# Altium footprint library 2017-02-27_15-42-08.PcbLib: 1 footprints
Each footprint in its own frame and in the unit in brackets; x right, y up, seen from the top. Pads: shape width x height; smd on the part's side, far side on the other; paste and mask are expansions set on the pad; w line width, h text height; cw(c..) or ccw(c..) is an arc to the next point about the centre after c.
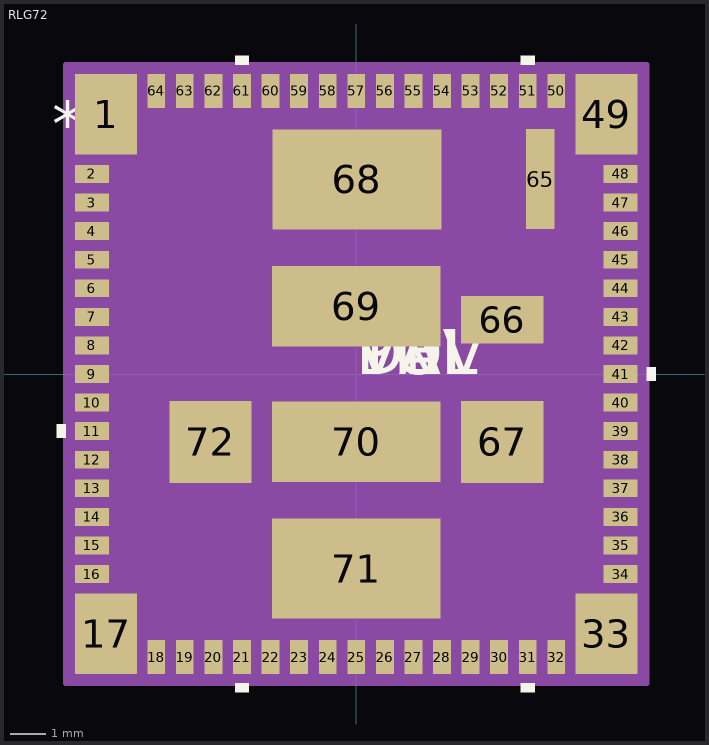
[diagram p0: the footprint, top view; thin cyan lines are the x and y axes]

## RLG72 [mm]
pads (72):
  rect 1.735x2.25 / inner round 1.524 / far side round 1.524 all layers, no hole: 1(-7.005,7.27) 17(-7.005,-7.27) 33(7.005,-7.27) 49(7.005,7.27)
  rect 0.95x0.5 smd paste-0.25: 2(-7.4,5.6) 3(-7.4,4.8) 4(-7.4,4) 5(-7.4,3.2) 6(-7.4,2.4) 7(-7.4,1.6) 8(-7.4,0.8) 9(-7.4,0) 10(-7.4,-0.8) 11(-7.4,-1.6) 12(-7.4,-2.4) 13(-7.4,-3.2) 14(-7.4,-4) 15(-7.4,-4.8) 16(-7.4,-5.6) 34(7.4,-5.6) 35(7.4,-4.8) 36(7.4,-4) 37(7.4,-3.2) 38(7.4,-2.4) 39(7.4,-1.6) 40(7.4,-0.8) 41(7.4,0) 42(7.4,0.8) 43(7.4,1.6) 44(7.4,2.4) 45(7.4,3.2) 46(7.4,4) 47(7.4,4.8) 48(7.4,5.6)
  rect 0.5x0.95 smd paste-0.25: 18(-5.6,-7.925) 19(-4.8,-7.925) 20(-4,-7.925) 21(-3.2,-7.925) 22(-2.4,-7.925) 23(-1.6,-7.925) 24(-0.8,-7.925) 25(0,-7.925) 26(0.8,-7.925) 27(1.6,-7.925) 28(2.4,-7.925) 29(3.2,-7.925) 30(4,-7.925) 31(4.8,-7.925) 32(5.6,-7.925) 50(5.6,7.925) 51(4.8,7.925) 52(4,7.925) 53(3.2,7.925) 54(2.4,7.925) 55(1.6,7.925) 56(0.8,7.925) 57(0,7.925) 58(-0.8,7.925) 59(-1.6,7.925) 60(-2.4,7.925) 61(-3.2,7.925) 62(-4,7.925) 63(-4.8,7.925) 64(-5.6,7.925)
  rect 0.8x2.8 smd paste-1.387: 65(5.15,5.453)
  rect 2.3x1.33 smd paste-1.137: 66(4.085,1.515)
  rect 2.3x2.3 smd paste-1.137: 67(4.085,-1.9) 72(-4.085,-1.9)
  rect 4.72x2.8 smd paste-2.347: 68(0.02,5.451) 71(0,-5.451)
  rect 4.72x2.25 smd paste-2.347: 69(0,1.9) 70(0,-1.9)
Top Overlay:
  region: -8.129,-1.409 -8.383,-1.409 -8.383,-1.79 -8.129,-1.79
  region: -3.009,-8.654 -3.39,-8.654 -3.39,-8.908 -3.009,-8.908
  region: 4.991,-8.654 4.61,-8.654 4.61,-8.908 4.991,-8.908
  region: 8.129,0.191 8.383,0.191 8.383,-0.191 8.129,-0.191
  region: 4.991,8.654 4.61,8.654 4.61,8.908 4.991,8.908
  region: -3.009,8.654 -3.39,8.654 -3.39,8.908 -3.009,8.908
  text "*" at -8.51,6.381 h1.27
  text "PN" at 0,0 h1.27
  text "DEV" at 0,0 h1.27
  text "VAL" at 0,0 h1.27
  text "TOL" at 0,0 h1.27
Top Paste:
  drawing of 109 lines, arcs and shapes, not listed
Top Solder:
  drawing of 64 lines, arcs and shapes, not listed
Mechanical 13:
  text "*" at -8.51,6.381 h1.27
  text "RefDes2" at 0,0 h1.27
Mechanical 15:
  region: 8.129,-8.654 -8.129,-8.654 -8.129,8.654 8.129,8.654
  lines w0.152: -8.129,-8.654 -8.129,8.654 8.129,8.654 8.129,-8.654 -8.129,-8.654
Mechanical 16:
  circle w0.152: c1.196,0.406 r0.076
  circle w0.152: c0.436,0.406 r0.076
  circle w0.152: c1.956,0.406 r0.076
  circle w0.152: c1.948,3.335 r0.076
  circle w0.152: c1.188,3.335 r0.076
  circle w0.152: c0.428,3.335 r0.076
  circle w0.152: c-0.332,3.335 r0.076
  circle w0.152: c-1.092,3.335 r0.076
  circle w0.152: c-1.852,3.335 r0.076
  circle w0.152: c-2.612,3.335 r0.076
  circle w0.152: c-2.604,2.6 r0.076
  circle w0.152: c-2.604,1.84 r0.076
  circle w0.152: c-2.604,1.097 r0.076
  circle w0.152: c-2.604,0.406 r0.076
  circle w0.152: c-1.844,0.406 r0.076
  circle w0.152: c-1.084,0.406 r0.076
  circle w0.152: c-0.324,0.406 r0.076
3D body: height 0.25, standoff 0, extent 0,0 0.254,0.254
